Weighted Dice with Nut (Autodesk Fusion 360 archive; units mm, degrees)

design "Weighted Dice with Nut" references "Hollow Cut", "Nut Implant"
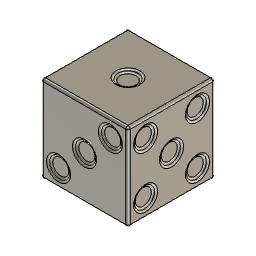
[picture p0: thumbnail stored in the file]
part number: 2025-09-26-16-34-02-084
sketch "Sketch1" plane through (0, 0, 0) normal (0, 0, 1) x axis (1, 0, 0)
  line L1 (19, 0) -> (0, 0)
  line L2 (19, 19) -> (19, 0)
  line L3 (0, 19) -> (19, 19)
  line L4 (0, 0) -> (0, 19)
  point P1 (0, 0)
  point P2 (0, 0)
  point P3 (19, 0)
  point P5 (0, 19)
  horizontal L1
  vertical L2
  horizontal L3
  vertical L4
  coincident P1 P2
  dimension "d1" distance P2 P3 = 19
  dimension "d2" distance P2 P5 = 19
extrude "Extrude1" new body sketch "Sketch1" along normal blind 19
sketch "Sketch2" plane through (0, 0, 19) normal (0, 0, 1) x axis (-1, 0, 0)
  line L1 (0, 0) -> (0, -19)
  line L2 (-19, 0) -> (0, 0)
  line L3 (-19, -19) -> (-19, 0)
  line L4 (0, -19) -> (-19, -19)
  line L5 (-19, -9.5) -> (0, -9.5)
  line L6 (-9.5, 0) -> (-9.5, -19)
  circle C1 centre (-9.5, -9.5) radius 2.25
  point P6 (0, -9.5)
  point P7 (-19, -9.5)
  point P8 (-9.5, -19)
  point P9 (-9.5, 0)
  point P10 (-9.5, -9.5)
  midpoint L1 P6
  midpoint L3 P7
  midpoint L4 P8
  midpoint L2 P9
  midpoint L5 P10
  dimension "d6" diameter C1 = 4.5
sketch "Sketch3" plane through (0, 0, 0) normal (0, 0, -1) x axis (1, 0, 0)
  line L1 (0, -19) -> (0, 0)
  line L2 (19, -19) -> (0, -19)
  line L3 (19, 0) -> (19, -19)
  line L4 (0, 0) -> (19, 0)
  line L5 (0, -15.1569) -> (3.8431, -15.1569)
  line L6 (3.8431, -19) -> (3.8431, -15.1569)
  line L7 (19, -15.1569) -> (15.1569, -15.1569)
  line L8 (15.1569, -19) -> (15.1569, -15.1569)
  line L9 (19, -3.8431) -> (15.1569, -3.8431)
  line L10 (15.1569, 0) -> (15.1569, -3.8431)
  line L11 (3.8431, 0) -> (3.8431, -3.8431)
  line L12 (0, -3.8431) -> (3.8431, -3.8431)
  line L13 (0, -9.5) -> (3.8431, -9.5)
  line L14 (19, -9.5) -> (15.1569, -9.5)
  line L15 (3.8431, -9.5) -> (3.8431, -3.8431)
  line L16 (3.8431, -9.5) -> (3.8431, -15.1569)
  line L17 (15.1569, -9.5) -> (15.1569, -3.8431)
  line L18 (15.1569, -9.5) -> (15.1569, -15.1569)
  circle C1 centre (3.8431, -3.8431) radius 2.25
  circle C2 centre (3.8431, -9.5) radius 2.25
  circle C3 centre (3.8431, -15.1569) radius 2.25
  circle C4 centre (15.1569, -3.8431) radius 2.25
  circle C5 centre (15.1569, -9.5) radius 2.25
  circle C6 centre (15.1569, -15.1569) radius 2.25
  point P8 (3.8431, -15.1569)
  point P13 (3.8431, -15.1569)
  point P14 (0, -15.1569)
  point P15 (3.8431, -15.1569)
  point P16 (3.8431, -19)
  point P11 (15.1569, -15.1569)
  point P17 (15.1569, -15.1569)
  point P18 (19, -15.1569)
  point P19 (15.1569, -15.1569)
  point P20 (15.1569, -19)
  point P9 (15.1569, -3.8431)
  point P21 (15.1569, -3.8431)
  point P22 (19, -3.8431)
  point P23 (15.1569, -3.8431)
  point P24 (15.1569, 0)
  point P6 (3.8431, -3.8431)
  point P25 (3.8431, -3.8431)
  point P26 (3.8431, 0)
  point P27 (3.8431, -3.8431)
  point P28 (0, -3.8431)
  point P7 (3.8431, -9.5)
  point P29 (3.8431, -9.5)
  point P30 (0, -9.5)
  point P10 (15.1569, -9.5)
  point P31 (15.1569, -9.5)
  point P32 (19, -9.5)
  point P33 (3.8431, -3.8431)
  point P34 (3.8431, -9.5)
  point P35 (3.8431, -15.1569)
  point P36 (3.8431, -9.5)
  point P37 (15.1569, -3.8431)
  point P38 (15.1569, -9.5)
  point P39 (15.1569, -15.1569)
  point P40 (15.1569, -9.5)
  point P12 (9.5, -9.5)
  coincident P8 P13
  coincident L1 P14
  perpendicular L1 L5
  coincident P8 P15
  coincident L2 P16
  perpendicular L2 L6
  coincident P11 P17
  coincident L3 P18
  perpendicular L3 L7
  coincident P11 P19
  coincident L2 P20
  perpendicular L2 L8
  coincident P9 P21
  coincident L3 P22
  perpendicular L3 L9
  coincident P9 P23
  coincident L4 P24
  perpendicular L4 L10
  coincident P6 P25
  coincident L4 P26
  perpendicular L4 L11
  coincident P6 P27
  coincident L1 P28
  perpendicular L1 L12
  equal L11 L12
  equal L9 L10
  equal L7 L8
  equal L5 L6
  coincident P7 P29
  coincident L1 P30
  perpendicular L1 L13
  coincident P10 P31
  coincident L3 P32
  perpendicular L3 L14
  equal L9 L14
  equal L12 L13
  coincident P6 P33
  coincident P7 P34
  coincident P8 P35
  coincident P7 P36
  coincident P9 P37
  coincident P10 P38
  coincident P11 P39
  coincident P10 P40
  equal L17 L18
  equal L15 L16
  dimension "d7" diameter C1 = 4.5
  dimension "d8" diameter C2 = 4.5
  dimension "d9" diameter C3 = 4.5
  dimension "d10" diameter C4 = 4.5
  dimension "d11" diameter C5 = 4.5
  dimension "d12" diameter C6 = 4.5
  dimension "d38" distance P6 P12 = 8
  dimension "d39" distance P8 P12 = 8
  dimension "d40" distance P9 P12 = 8
  dimension "d41" distance P11 P12 = 8
sketch "Sketch4" plane through (0, 0, 0) normal (-1, 0, 0) x axis (0, -1, 0)
  line L1 (0, 0) -> (-19, 0)
  line L2 (0, 19) -> (0, 0)
  line L3 (-19, 19) -> (0, 19)
  line L4 (-19, 0) -> (-19, 19)
  line L5 (0, 15.1569) -> (-3.8431, 15.1569)
  line L6 (-3.8431, 19) -> (-3.8431, 15.1569)
  line L7 (-19, 9.5) -> (0, 9.5)
  line L8 (-9.5, 0) -> (-9.5, 19)
  line L9 (-19, 3.8431) -> (-15.1569, 3.8431)
  line L10 (-15.1569, 0) -> (-15.1569, 3.8431)
  circle C1 centre (-3.8431, 15.1569) radius 2.25
  circle C2 centre (-15.1569, 3.8431) radius 2.25
  point P6 (-3.8431, 15.1569)
  point P8 (-3.8431, 15.1569)
  point P9 (0, 15.1569)
  point P10 (-3.8431, 15.1569)
  point P11 (-3.8431, 19)
  point P12 (0, 9.5)
  point P13 (-19, 9.5)
  point P14 (-9.5, 19)
  point P15 (-9.5, 0)
  point P7 (-15.1569, 3.8431)
  point P16 (-15.1569, 3.8431)
  point P17 (-19, 3.8431)
  point P18 (-15.1569, 3.8431)
  point P19 (-15.1569, 0)
  point P20 (-9.5, 9.5)
  coincident P6 P8
  coincident L2 P9
  perpendicular L2 L5
  coincident P6 P10
  coincident L3 P11
  perpendicular L3 L6
  midpoint L2 P12
  midpoint L4 P13
  midpoint L3 P14
  midpoint L1 P15
  coincident P7 P16
  coincident L4 P17
  perpendicular L4 L9
  coincident P7 P18
  coincident L1 P19
  perpendicular L1 L10
  equal L5 L6
  equal L9 L10
  midpoint L8 P20
  dimension "d13" diameter C1 = 4.5
  dimension "d14" diameter C2 = 4.5
  dimension "d43" distance P6 P20 = 8
  dimension "d44" distance P7 P20 = 8
sketch "Sketch5" plane through (0, 0, 0) normal (0, -1, 0) x axis (1, 0, 0)
  line L1 (19, 0) -> (0, 0)
  line L2 (19, 19) -> (19, 0)
  line L3 (0, 19) -> (19, 19)
  line L4 (0, 0) -> (0, 19)
  line L5 (19, 9.5) -> (0, 9.5)
  line L6 (9.5, 0) -> (9.5, 19)
  line L7 (0, 19) -> (0, 0)
  line L8 (3.8431, 0) -> (3.8431, 3.8431)
  line L9 (0, 3.8431) -> (3.8431, 3.8431)
  line L10 (15.1569, 19) -> (15.1569, 15.1569)
  line L11 (19, 15.1569) -> (15.1569, 15.1569)
  circle C1 centre (9.5, 9.5) radius 2.25
  circle C2 centre (15.1569, 15.1569) radius 2.25
  circle C3 centre (3.8431, 3.8431) radius 2.25
  point P6 (0, 9.5)
  point P7 (19, 9.5)
  point P8 (9.5, 19)
  point P9 (9.5, 0)
  point P10 (9.5, 9.5)
  point P12 (3.8431, 3.8431)
  point P15 (3.8431, 3.8431)
  point P16 (3.8431, 0)
  point P17 (3.8431, 3.8431)
  point P18 (0, 3.8431)
  point P11 (15.1569, 15.1569)
  point P19 (15.1569, 15.1569)
  point P20 (15.1569, 19)
  point P21 (15.1569, 15.1569)
  point P22 (19, 15.1569)
  midpoint L4 P6
  midpoint L2 P7
  midpoint L3 P8
  midpoint L1 P9
  midpoint L5 P10
  coincident P12 P15
  coincident L1 P16
  perpendicular L1 L8
  coincident P12 P17
  coincident L4 P18
  perpendicular L4 L9
  equal L8 L9
  coincident P11 P19
  coincident L3 P20
  perpendicular L3 L10
  coincident P11 P21
  coincident L2 P22
  perpendicular L2 L11
  equal L10 L11
  dimension "d15" diameter C1 = 4.5
  dimension "d16" diameter C2 = 4.5
  dimension "d17" diameter C3 = 4.5
  dimension "d27" distance P10 P12 = 8
  dimension "d28" distance P10 P11 = 8
  dimension "d29" distance P10 L7 = 9.5
sketch "Sketch6" plane through (19, 0, 0) normal (1, 0, 0) x axis (0, 1, 0)
  line L1 (19, 0) -> (0, 0)
  line L2 (19, 19) -> (19, 0)
  line L3 (0, 19) -> (19, 19)
  line L4 (0, 0) -> (0, 19)
  line L5 (19, 9.5) -> (0, 9.5)
  line L6 (9.5, 0) -> (9.5, 19)
  line L7 (0, 12.9069) -> (0, 17.4069)
  line L8 (0, 19) -> (19, 19)
  line L9 (3.8431, 19) -> (3.8431, 15.1569)
  line L10 (0, 15.1569) -> (3.8431, 15.1569)
  line L11 (15.1569, 19) -> (15.1569, 15.1569)
  line L12 (19, 15.1569) -> (15.1569, 15.1569)
  line L13 (0, 3.8431) -> (3.8431, 3.8431)
  line L14 (3.8431, 0) -> (3.8431, 3.8431)
  line L15 (19, 3.8431) -> (15.1569, 3.8431)
  line L16 (15.1569, 0) -> (15.1569, 3.8431)
  circle C1 centre (9.5, 9.5) radius 2.25
  circle C2 centre (3.8431, 15.1569) radius 2.25
  circle C3 centre (3.8431, 3.8431) radius 2.25
  circle C4 centre (15.1569, 15.1569) radius 2.25
  circle C5 centre (15.1569, 3.8431) radius 2.25
  point P6 (0, 9.5)
  point P7 (19, 9.5)
  point P8 (9.5, 19)
  point P9 (9.5, 0)
  point P10 (9.5, 9.5)
  point P11 (3.8431, 15.1569)
  point P19 (3.8431, 15.1569)
  point P20 (3.8431, 19)
  point P21 (3.8431, 15.1569)
  point P22 (0, 15.1569)
  point P13 (15.1569, 15.1569)
  point P23 (15.1569, 15.1569)
  point P24 (15.1569, 19)
  point P25 (15.1569, 15.1569)
  point P26 (19, 15.1569)
  point P12 (3.8431, 3.8431)
  point P27 (3.8431, 3.8431)
  point P28 (0, 3.8431)
  point P29 (3.8431, 3.8431)
  point P30 (3.8431, 0)
  point P14 (15.1569, 3.8431)
  point P31 (15.1569, 3.8431)
  point P32 (19, 3.8431)
  point P33 (15.1569, 3.8431)
  point P34 (15.1569, 0)
  midpoint L4 P6
  midpoint L2 P7
  midpoint L3 P8
  midpoint L1 P9
  midpoint L6 P10
  coincident P11 P19
  coincident L8 P20
  perpendicular L8 L9
  coincident P11 P21
  equal L9 L10
  coincident L7 P22
  coincident P13 P23
  coincident L8 P24
  perpendicular L8 L11
  coincident P13 P25
  coincident L2 P26
  perpendicular L2 L12
  equal L11 L12
  coincident P12 P27
  coincident L4 P28
  perpendicular L4 L13
  coincident P12 P29
  coincident L1 P30
  perpendicular L1 L14
  equal L13 L14
  coincident P14 P31
  coincident L2 P32
  perpendicular L2 L15
  coincident P14 P33
  coincident L1 P34
  perpendicular L1 L16
  equal L15 L16
  dimension "d18" diameter C1 = 4.5
  dimension "d19" diameter C2 = 4.5
  dimension "d20" diameter C3 = 4.5
  dimension "d21" diameter C4 = 4.5
  dimension "d22" diameter C5 = 4.5
  dimension "d30" distance P10 P11 = 8
  dimension "d31" distance P10 P13 = 8
  dimension "d32" distance P10 P14 = 8
  dimension "d33" distance P10 P12 = 8
  dimension "d37" angle L9 L10 = 90
sketch "Sketch7" plane through (0, 19, 0) normal (0, 1, 0) x axis (-1, 0, 0)
  line L1 (0, 0) -> (-19, 0)
  line L2 (0, 19) -> (0, 0)
  line L3 (-19, 19) -> (0, 19)
  line L4 (-19, 0) -> (-19, 19)
  line L5 (-15.1569, 0) -> (-15.1569, 3.8431)
  line L6 (-19, 3.8431) -> (-15.1569, 3.8431)
  line L7 (0, 9.5) -> (-19, 9.5)
  line L8 (-9.5, 0) -> (-9.5, 19)
  line L9 (-15.1569, 19) -> (-15.1569, 15.1569)
  line L10 (-19, 15.1569) -> (-15.1569, 15.1569)
  line L11 (0, 15.1569) -> (-3.8431, 15.1569)
  line L12 (-3.8431, 19) -> (-3.8431, 15.1569)
  line L13 (0, 3.8431) -> (-3.8431, 3.8431)
  line L14 (-3.8431, 0) -> (-3.8431, 3.8431)
  circle C1 centre (-15.1569, 15.1569) radius 2.25
  circle C2 centre (-15.1569, 3.8431) radius 2.25
  circle C3 centre (-3.8431, 15.1569) radius 2.25
  circle C4 centre (-3.8431, 3.8431) radius 2.25
  point P7 (-15.1569, 3.8431)
  point P11 (-15.1569, 3.8431)
  point P12 (-15.1569, 0)
  point P13 (-15.1569, 3.8431)
  point P14 (-19, 3.8431)
  point P15 (-19, 9.5)
  point P16 (0, 9.5)
  point P17 (-9.5, 19)
  point P18 (-9.5, 0)
  point P6 (-15.1569, 15.1569)
  point P19 (-15.1569, 15.1569)
  point P20 (-15.1569, 19)
  point P21 (-15.1569, 15.1569)
  point P22 (-19, 15.1569)
  point P8 (-3.8431, 15.1569)
  point P23 (-3.8431, 15.1569)
  point P24 (0, 15.1569)
  point P25 (-3.8431, 15.1569)
  point P26 (-3.8431, 19)
  point P9 (-3.8431, 3.8431)
  point P27 (-3.8431, 3.8431)
  point P28 (0, 3.8431)
  point P29 (-3.8431, 3.8431)
  point P30 (-3.8431, 0)
  point P10 (-9.5, 9.5)
  coincident P7 P11
  coincident L1 P12
  perpendicular L1 L5
  coincident P7 P13
  coincident L4 P14
  perpendicular L4 L6
  midpoint L4 P15
  midpoint L2 P16
  midpoint L3 P17
  midpoint L1 P18
  equal L5 L6
  coincident P6 P19
  coincident L3 P20
  perpendicular L3 L9
  coincident P6 P21
  coincident L4 P22
  perpendicular L4 L10
  equal L9 L10
  coincident P8 P23
  coincident L2 P24
  perpendicular L2 L11
  coincident P8 P25
  coincident L3 P26
  perpendicular L3 L12
  equal L11 L12
  coincident P9 P27
  coincident L2 P28
  perpendicular L2 L13
  coincident P9 P29
  coincident L1 P30
  perpendicular L1 L14
  equal L13 L14
  dimension "d23" diameter C1 = 4.5
  dimension "d24" diameter C2 = 4.5
  dimension "d25" diameter C3 = 4.5
  dimension "d26" diameter C4 = 4.5
  dimension "d45" distance P6 P10 = 8
  dimension "d46" distance P7 P10 = 8
  dimension "d48" distance P8 P10 = 8
  dimension "d78" distance P9 P10 = 8
extrude "Extrude2" cut sketch "Sketch2" profile of C1 against normal blind 0.5
fillet "Fillet1" radius 0.5
extrude "Extrude3" cut sketch "Sketch6" profile of C1 C2 C3 C4 C5 against normal blind 0.5
fillet "Fillet2" radius 0.5
extrude "Extrude4" cut sketch "Sketch7" profile of C1 C2 C3 C4 against normal blind 0.5
fillet "Fillet3" radius 0.5
extrude "Extrude5" cut sketch "Sketch4" profile of C1 C2 against normal blind 0.5
fillet "Fillet4" radius 0.5
extrude "Extrude6" cut sketch "Sketch5" profile of C1 C2 C3 against normal blind 0.5
fillet "Fillet5" radius 0.5
extrude "Extrude7" cut sketch "Sketch3" profile of C1 C2 C3 C4 C5 C6 against normal blind 0.5
fillet "Fillet6" radius 0.5
fillet "Fillet7" radius 0.5
fillet "Fillet8" radius 0.5
component_insert "Component Insert1"
work_plane "WorkPlane1"
combine "Combine2"
work_plane "WorkPlane2"
component_insert "Component Insert8"
combine "Combine8"

design "Hollow Cut"
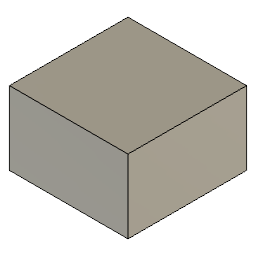
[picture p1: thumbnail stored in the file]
part number: 2025-09-27-23-07-06-343
sketch "Sketch1" plane through (0, 0, 0) normal (0, 0, 1) x axis (1, 0, 0)
  line L1 (17, 0) -> (0, 0)
  line L2 (17, 17) -> (17, 0)
  line L3 (0, 17) -> (17, 17)
  line L4 (0, 0) -> (0, 17)
  point P1 (0, 0)
  point P2 (0, 0)
  point P3 (17, 0)
  point P5 (0, 17)
  horizontal L1
  vertical L2
  horizontal L3
  vertical L4
  coincident P1 P2
  dimension "d1" distance P2 P3 = 17
  dimension "d2" distance P2 P5 = 17
extrude "Extrude1" new body sketch "Sketch1" along normal blind 10.53

design "Nut Implant"
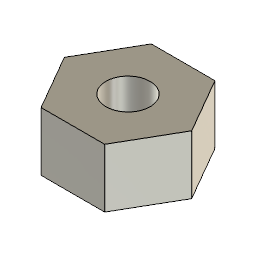
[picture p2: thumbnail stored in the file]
part number: 2025-09-29-22-40-45-153
sketch "Sketch1" plane through (0, 0, 0) normal (0, 0, 1) x axis (1, 0, 0)
  line L1 (-3.25, 5.6292) -> (3.25, 5.6292)
  line L2 (-6.5, 0) -> (-3.25, 5.6292)
  line L3 (-3.25, -5.6292) -> (-6.5, 0)
  line L4 (3.25, -5.6292) -> (-3.25, -5.6292)
  line L5 (6.5, 0) -> (3.25, -5.6292)
  line L6 (3.25, 5.6292) -> (6.5, 0)
  point P1 (0, 0)
  point P8 (0, 0)
  point P7 (6.5, 0)
  coincident P1 P8
  horizontal L1
  dimension "d8" distance P7 P8 = 6.5
extrude "Extrude1" new body sketch "Sketch1" along normal blind 6
sketch "Sketch2" plane through (0, 0, 6) normal (0, 0, 1) x axis (-1, 0, 0)
  line L1 (-3.25, -5.6292) -> (-6.5, 0)
  line L2 (3.25, -5.6292) -> (-3.25, -5.6292)
  line L3 (6.5, 0) -> (3.25, -5.6292)
  line L4 (3.25, 5.6292) -> (6.5, 0)
  line L5 (-3.25, 5.6292) -> (3.25, 5.6292)
  line L6 (-6.5, 0) -> (-3.25, 5.6292)
  circle C1 centre (0, 0) radius 2.25
  point P1 (0, 0)
  point P8 (0, 0)
  coincident P1 P8
  dimension "d5" diameter C1 = 4.5
extrude "Extrude2" cut sketch "Sketch2" profile of C1 against normal blind 6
